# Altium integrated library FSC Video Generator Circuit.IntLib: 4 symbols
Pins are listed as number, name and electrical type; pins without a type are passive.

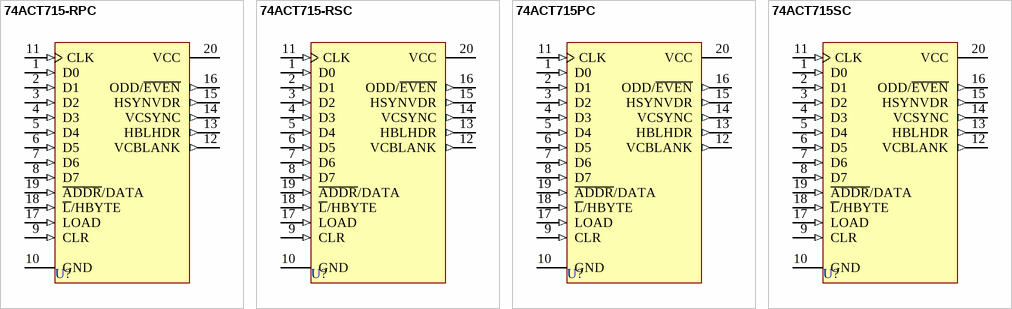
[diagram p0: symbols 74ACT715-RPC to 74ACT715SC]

## 74ACT715-RPC
designator U?
Programmable Video Sync Generator
footprint N20A (DIP; 20 Leads; Row Spacing 7.62 mm; Pitch 2.54 mm)
3D model N20A (DIP; 20 Leads; Row Spacing 7.62 mm; Pitch 2.54 mm)
signal-integrity model 74ACT715-RPC
pins: 1 D0 (in), 2 D1 (in), 3 D2 (in), 4 D3 (in), 5 D4 (in), 6 D5 (in), 7 D6 (in), 8 D7 (in), 9 CLR (in), 10 GND (power), 11 CLK (in), 12 VCBLANK (out), 13 HBLHDR (out), 14 VCSYNC (out), 15 HSYNVDR (out), 16 ODD/~{EVEN} (out), 17 LOAD (in), 18 ~{L}/HBYTE (in), 19 ~{ADDR}/DATA (in), 20 VCC (power)

## 74ACT715-RSC
designator U?
Programmable Video Sync Generator
footprint M20B_N (SOIC, 20-Leads, Body 12.8x7.5mm, Pitch 1.27mm, IPC Medium Density)
footprint M20B_L (SOIC, 20-Leads, Body 12.8x7.5mm, Pitch 1.27mm, IPC High Density)
footprint M20B_M (SOIC, 20-Leads, Body 12.8x7.5mm, Pitch 1.27mm, IPC Low Density)
3D model M20B (20-Pin Small Outline Integrated Circuit 1.27 mm Pitch)
signal-integrity model 74ACT715-RSC
pins: 1 D0 (in), 2 D1 (in), 3 D2 (in), 4 D3 (in), 5 D4 (in), 6 D5 (in), 7 D6 (in), 8 D7 (in), 9 CLR (in), 10 GND (power), 11 CLK (in), 12 VCBLANK (out), 13 HBLHDR (out), 14 VCSYNC (out), 15 HSYNVDR (out), 16 ODD/~{EVEN} (out), 17 LOAD (in), 18 ~{L}/HBYTE (in), 19 ~{ADDR}/DATA (in), 20 VCC (power)

## 74ACT715PC
designator U?
Programmable Video Sync Generator
footprint N20A (DIP; 20 Leads; Row Spacing 7.62 mm; Pitch 2.54 mm)
3D model N20A (DIP; 20 Leads; Row Spacing 7.62 mm; Pitch 2.54 mm)
signal-integrity model 74ACT715PC
pins: 1 D0 (in), 2 D1 (in), 3 D2 (in), 4 D3 (in), 5 D4 (in), 6 D5 (in), 7 D6 (in), 8 D7 (in), 9 CLR (in), 10 GND (power), 11 CLK (in), 12 VCBLANK (out), 13 HBLHDR (out), 14 VCSYNC (out), 15 HSYNVDR (out), 16 ODD/~{EVEN} (out), 17 LOAD (in), 18 ~{L}/HBYTE (in), 19 ~{ADDR}/DATA (in), 20 VCC (power)

## 74ACT715SC
designator U?
Programmable Video Sync Generator
footprint M20B_N (SOIC, 20-Leads, Body 12.8x7.5mm, Pitch 1.27mm, IPC Medium Density)
footprint M20B_L (SOIC, 20-Leads, Body 12.8x7.5mm, Pitch 1.27mm, IPC High Density)
footprint M20B_M (SOIC, 20-Leads, Body 12.8x7.5mm, Pitch 1.27mm, IPC Low Density)
3D model M20B (20-Pin Small Outline Integrated Circuit 1.27 mm Pitch)
signal-integrity model 74ACT715SC
pins: 1 D0 (in), 2 D1 (in), 3 D2 (in), 4 D3 (in), 5 D4 (in), 6 D5 (in), 7 D6 (in), 8 D7 (in), 9 CLR (in), 10 GND (power), 11 CLK (in), 12 VCBLANK (out), 13 HBLHDR (out), 14 VCSYNC (out), 15 HSYNVDR (out), 16 ODD/~{EVEN} (out), 17 LOAD (in), 18 ~{L}/HBYTE (in), 19 ~{ADDR}/DATA (in), 20 VCC (power)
